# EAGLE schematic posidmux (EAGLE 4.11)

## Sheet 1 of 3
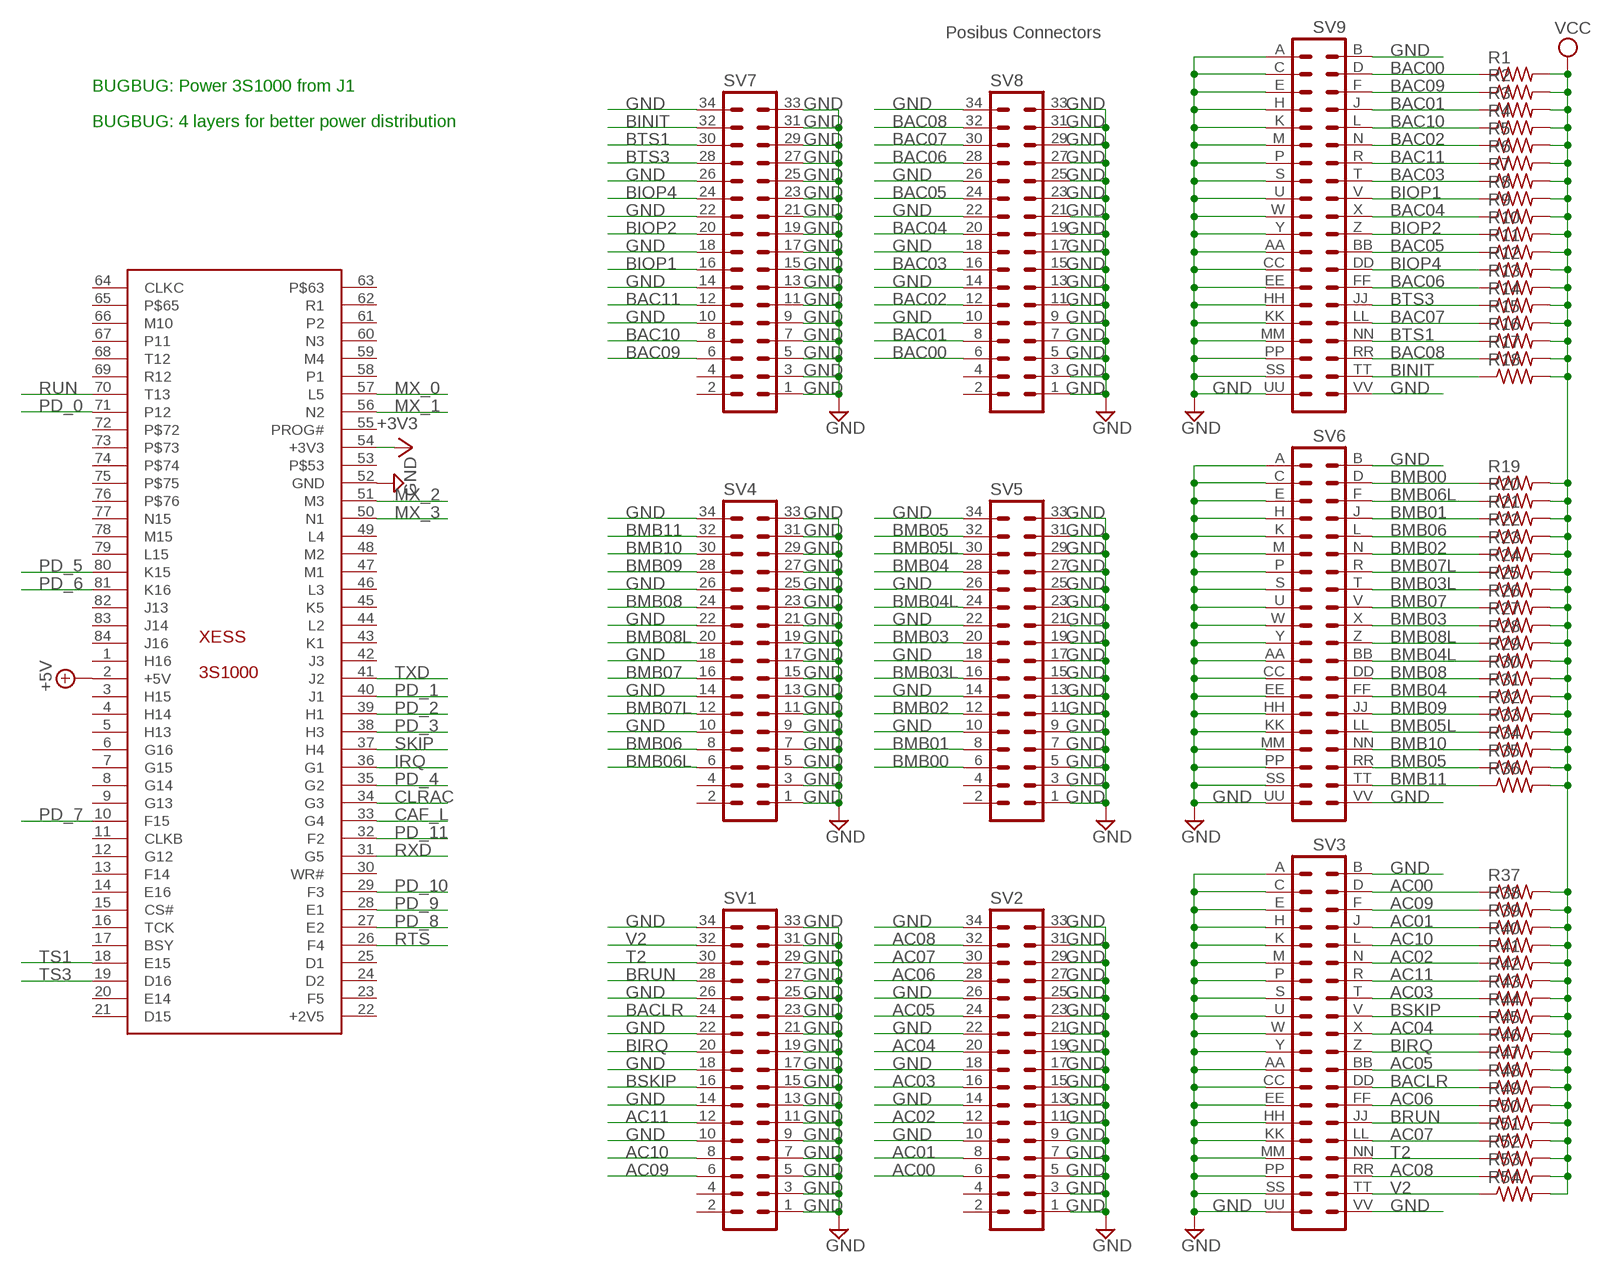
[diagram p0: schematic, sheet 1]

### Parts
R1  R-US_0207/10  [0207/10]
R2  R-US_0207/10  [0207/10]
R3  R-US_0207/10  [0207/10]
R4  R-US_0207/10  [0207/10]
R5  R-US_0207/10  [0207/10]
R6  R-US_0207/10  [0207/10]
R7  R-US_0207/10  [0207/10]
R8  R-US_0207/10  [0207/10]
R9  R-US_0207/10  [0207/10]
R10  R-US_0207/10  [0207/10]
R11  R-US_0207/10  [0207/10]
R12  R-US_0207/10  [0207/10]
R13  R-US_0207/10  [0207/10]
R14  R-US_0207/10  [0207/10]
R15  R-US_0207/10  [0207/10]
R16  R-US_0207/10  [0207/10]
R17  R-US_0207/10  [0207/10]
R18  R-US_0207/10  [0207/10]
R19  R-US_0207/10  [0207/10]
R20  R-US_0207/10  [0207/10]
R21  R-US_0207/10  [0207/10]
R22  R-US_0207/10  [0207/10]
R23  R-US_0207/10  [0207/10]
R24  R-US_0207/10  [0207/10]
R25  R-US_0207/10  [0207/10]
R26  R-US_0207/10  [0207/10]
R27  R-US_0207/10  [0207/10]
R28  R-US_0207/10  [0207/10]
R29  R-US_0207/10  [0207/10]
R30  R-US_0207/10  [0207/10]
R31  R-US_0207/10  [0207/10]
R32  R-US_0207/10  [0207/10]
R33  R-US_0207/10  [0207/10]
R34  R-US_0207/10  [0207/10]
R35  R-US_0207/10  [0207/10]
R36  R-US_0207/10  [0207/10]
R37  R-US_0207/10  [0207/10]
R38  R-US_0207/10  [0207/10]
R39  R-US_0207/10  [0207/10]
R40  R-US_0207/10  [0207/10]
R41  R-US_0207/10  [0207/10]
R42  R-US_0207/10  [0207/10]
R43  R-US_0207/10  [0207/10]
R44  R-US_0207/10  [0207/10]
R45  R-US_0207/10  [0207/10]
R46  R-US_0207/10  [0207/10]
R47  R-US_0207/10  [0207/10]
R48  R-US_0207/10  [0207/10]
R49  R-US_0207/10  [0207/10]
R50  R-US_0207/10  [0207/10]
R51  R-US_0207/10  [0207/10]
R52  R-US_0207/10  [0207/10]
R53  R-US_0207/10  [0207/10]
R54  R-US_0207/10  [0207/10]
SV1  MA17-2  [MA17-2]
SV2  MA17-2  [MA17-2]
SV3  DEC40PIN  [DEC40PIN]
SV4  MA17-2  [MA17-2]
SV5  MA17-2  [MA17-2]
SV6  DEC40PIN  [DEC40PIN]
SV7  MA17-2  [MA17-2]
SV8  MA17-2  [MA17-2]
SV9  DEC40PIN  [DEC40PIN]
XESS  3S1000  [3S1000]

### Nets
+3V3: XESS.54(+3V3) ; also sheet 3
+5V: XESS.2(+5V)
AC00: R37.1 SV2.6 SV3.D ; also sheet 3
AC01: R39.1 SV2.8 SV3.J ; also sheet 3
AC02: R41.1 SV2.12 SV3.N ; also sheet 3
AC03: R43.1 SV2.16 SV3.T ; also sheet 3
AC04: R45.1 SV2.20 SV3.X ; also sheet 3
AC05: R47.1 SV2.24 SV3.BB ; also sheet 3
AC06: R49.1 SV2.28 SV3.FF ; also sheet 3
AC07: R51.1 SV2.30 SV3.LL ; also sheet 3
AC08: R53.1 SV2.32 SV3.RR ; also sheet 3
AC09: R38.1 SV1.6 SV3.F ; also sheet 3
AC10: R40.1 SV1.8 SV3.L ; also sheet 3
AC11: R42.1 SV1.12 SV3.R ; also sheet 3
BAC00: R1.1 SV8.6 SV9.D ; also sheet 2
BAC01: R3.1 SV8.8 SV9.J ; also sheet 2
BAC02: R5.1 SV8.12 SV9.N ; also sheet 2
BAC03: R7.1 SV8.16 SV9.T ; also sheet 2
BAC04: R9.1 SV8.20 SV9.X ; also sheet 2
BAC05: R11.1 SV8.24 SV9.BB ; also sheet 2
BAC06: R13.1 SV8.28 SV9.FF ; also sheet 2
BAC07: R15.1 SV8.30 SV9.LL
BAC08: R17.1 SV8.32 SV9.RR ; also sheet 2
BAC09: R2.1 SV7.6 SV9.F ; also sheet 2
BAC10: R4.1 SV7.8 SV9.L ; also sheet 2
BAC11: R6.1 SV7.12 SV9.R ; also sheet 2
BACLR: R48.1 SV1.24 SV3.DD ; also sheet 3
BINIT: R18.1 SV7.32 SV9.TT ; also sheet 3
BIOP1: R8.1 SV7.16 SV9.V ; also sheet 3
BIOP2: R10.1 SV7.20 SV9.Z ; also sheet 3
BIOP4: R12.1 SV7.24 SV9.DD ; also sheet 3
BIRQ: R46.1 SV1.20 SV3.Z ; also sheet 3
BMB00: R19.1 SV5.6 SV6.D ; also sheet 2
BMB01: R21.1 SV5.8 SV6.J ; also sheet 2
BMB02: R23.1 SV5.12 SV6.N ; also sheet 2
BMB03: R27.1 SV5.20 SV6.X ; also sheet 2
BMB03L: R25.1 SV5.16 SV6.T ; also sheet 2
BMB04: R31.1 SV5.28 SV6.FF ; also sheet 2
BMB04L: R29.1 SV5.24 SV6.BB ; also sheet 2
BMB05: R35.1 SV5.32 SV6.RR ; also sheet 2
BMB05L: R33.1 SV5.30 SV6.LL ; also sheet 2
BMB06: R22.1 SV4.8 SV6.L ; also sheet 2
BMB06L: R20.1 SV4.6 SV6.F ; also sheet 2
BMB07: R26.1 SV4.16 SV6.V ; also sheet 2
BMB07L: R24.1 SV4.12 SV6.R ; also sheet 2
BMB08: R30.1 SV4.24 SV6.DD ; also sheet 2
BMB08L: R28.1 SV4.20 SV6.Z ; also sheet 2
BMB09: R32.1 SV4.28 SV6.JJ ; also sheet 2
BMB10: R34.1 SV4.30 SV6.NN ; also sheet 2
BMB11: R36.1 SV4.32 SV6.TT ; also sheet 2
BRUN: R50.1 SV1.28 SV3.JJ ; also sheet 3
BSKIP: R44.1 SV1.16 SV3.V ; also sheet 3
BTS1: R16.1 SV7.30 SV9.NN ; also sheet 3
BTS3: R14.1 SV7.28 SV9.JJ ; also sheet 3
CAF_L: XESS.33(G4) ; also sheet 3
CLRAC: XESS.34(G3) ; also sheet 3
GND: SV1.1 SV1.3 SV1.5 SV1.7 SV1.9 SV1.10 SV1.11 SV1.13 SV1.14 SV1.15 SV1.17 SV1.18 SV1.19 SV1.21 SV1.22 SV1.23 SV1.25 SV1.26 SV1.27 SV1.29 SV1.31 SV1.33 SV1.34 SV2.1 SV2.3 SV2.5 SV2.7 SV2.9 SV2.10 SV2.11 SV2.13 SV2.14 SV2.15 SV2.17 SV2.18 SV2.19 SV2.21 SV2.22 SV2.23 SV2.25 SV2.26 SV2.27 SV2.29 SV2.31 SV2.33 SV2.34 SV3.A SV3.AA SV3.B SV3.C SV3.CC SV3.E SV3.EE SV3.H SV3.HH SV3.K SV3.KK SV3.M SV3.MM SV3.P SV3.PP SV3.S SV3.SS SV3.U SV3.UU SV3.VV SV3.W SV3.Y SV4.1 SV4.3 SV4.5 SV4.7 SV4.9 SV4.10 SV4.11 SV4.13 SV4.14 SV4.15 SV4.17 SV4.18 SV4.19 SV4.21 SV4.22 SV4.23 SV4.25 SV4.26 SV4.27 SV4.29 SV4.31 SV4.33 SV4.34 SV5.1 SV5.3 SV5.5 SV5.7 SV5.9 SV5.10 SV5.11 SV5.13 SV5.14 SV5.15 SV5.17 SV5.18 SV5.19 SV5.21 SV5.22 SV5.23 SV5.25 SV5.26 SV5.27 SV5.29 SV5.31 SV5.33 SV5.34 SV6.A SV6.AA SV6.B SV6.C SV6.CC SV6.E SV6.EE SV6.H SV6.HH SV6.K SV6.KK SV6.M SV6.MM SV6.P SV6.PP SV6.S SV6.SS SV6.U SV6.UU SV6.VV SV6.W SV6.Y SV7.1 SV7.3 SV7.5 SV7.7 SV7.9 SV7.10 SV7.11 SV7.13 SV7.14 SV7.15 SV7.17 SV7.18 SV7.19 SV7.21 SV7.22 SV7.23 SV7.25 SV7.26 SV7.27 SV7.29 SV7.31 SV7.33 SV7.34 SV8.1 SV8.3 SV8.5 SV8.7 SV8.9 SV8.10 SV8.11 SV8.13 SV8.14 SV8.15 SV8.17 SV8.18 SV8.19 SV8.21 SV8.22 SV8.23 SV8.25 SV8.26 SV8.27 SV8.29 SV8.31 SV8.33 SV8.34 SV9.A SV9.AA SV9.B SV9.C SV9.CC SV9.E SV9.EE SV9.H SV9.HH SV9.K SV9.KK SV9.M SV9.MM SV9.P SV9.PP SV9.S SV9.SS SV9.U SV9.UU SV9.VV SV9.W SV9.Y XESS.52(GND) ; also sheet 2,3
IRQ: XESS.36(G1) ; also sheet 3
MX_0: XESS.57(L5) ; also sheet 2
MX_1: XESS.56(N2) ; also sheet 2
MX_2: XESS.51(M3) ; also sheet 2
MX_3: XESS.50(N1) ; also sheet 2
PD_0: XESS.71(P12) ; also sheet 2,3
PD_1: XESS.40(J1) ; also sheet 2,3
PD_2: XESS.39(H1) ; also sheet 2,3
PD_3: XESS.38(H3) ; also sheet 2,3
PD_4: XESS.35(G2) ; also sheet 2,3
PD_5: XESS.80(K15) ; also sheet 2,3
PD_6: XESS.81(K16) ; also sheet 2,3
PD_7: XESS.10(F15) ; also sheet 2,3
PD_8: XESS.27(E2) ; also sheet 2,3
PD_9: XESS.28(E1) ; also sheet 2,3
PD_10: XESS.29(F3) ; also sheet 2,3
PD_11: XESS.32(F2) ; also sheet 2,3
RTS: XESS.26(F4) ; also sheet 3
RUN: XESS.70(T13) ; also sheet 3
RXD: XESS.31(G5) ; also sheet 3
SKIP: XESS.37(H4) ; also sheet 3
T2: R52.1 SV1.30 SV3.NN
TS1: XESS.18(E15) ; also sheet 3
TS3: XESS.19(D16) ; also sheet 3
TXD: XESS.41(J2) ; also sheet 3
V2: R54.1 SV1.32 SV3.TT
VCC: R1.2 R2.2 R3.2 R4.2 R5.2 R6.2 R7.2 R8.2 R9.2 R10.2 R11.2 R12.2 R13.2 R14.2 R15.2 R16.2 R17.2 R18.2 R19.2 R20.2 R21.2 R22.2 R23.2 R24.2 R25.2 R26.2 R27.2 R28.2 R29.2 R30.2 R31.2 R32.2 R33.2 R34.2 R35.2 R36.2 R37.2 R38.2 R39.2 R40.2 R41.2 R42.2 R43.2 R44.2 R45.2 R46.2 R47.2 R48.2 R49.2 R50.2 R51.2 R52.2 R53.2 R54.2 ; also sheet 2,3
Unconnected: SV1.2 SV1.4 SV2.2 SV2.4 SV4.2 SV4.4 SV5.2 SV5.4 SV7.2 SV7.4 SV8.2 SV8.4 XESS.1(H16) XESS.3(H15) XESS.4(H14) XESS.5(H13) XESS.6(G16) XESS.7(G15) XESS.8(G14) XESS.9(G13) XESS.11(CLKB) XESS.12(G12) XESS.13(F14) XESS.14(E16) XESS.15(CS#) XESS.16(TCK) XESS.17(BSY) XESS.20(E14) XESS.21(D15) XESS.23(F5) XESS.24(D2) XESS.25(D1) XESS.30(WR#) XESS.42(J3) XESS.43(K1) XESS.44(L2) XESS.45(K5) XESS.46(L3) XESS.47(M1) XESS.48(M2) XESS.49(L4) XESS.53 XESS.55(PROG#) XESS.58(P1) XESS.59(M4) XESS.60(N3) XESS.61(P2) XESS.62(R1) XESS.63 XESS.64(CLKC) XESS.65 XESS.66(M10) XESS.67(P11) XESS.68(T12) XESS.69(R12) XESS.72 XESS.73 XESS.74 XESS.75 XESS.76 XESS.77(N15) XESS.78(M15) XESS.79(L15) XESS.82(J13) XESS.83(J14) XESS.84(J16)

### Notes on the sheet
- Posibus Connectors
- BUGBUG: Power 3S1000 from J1
- BUGBUG: 4 layers for better power distribution

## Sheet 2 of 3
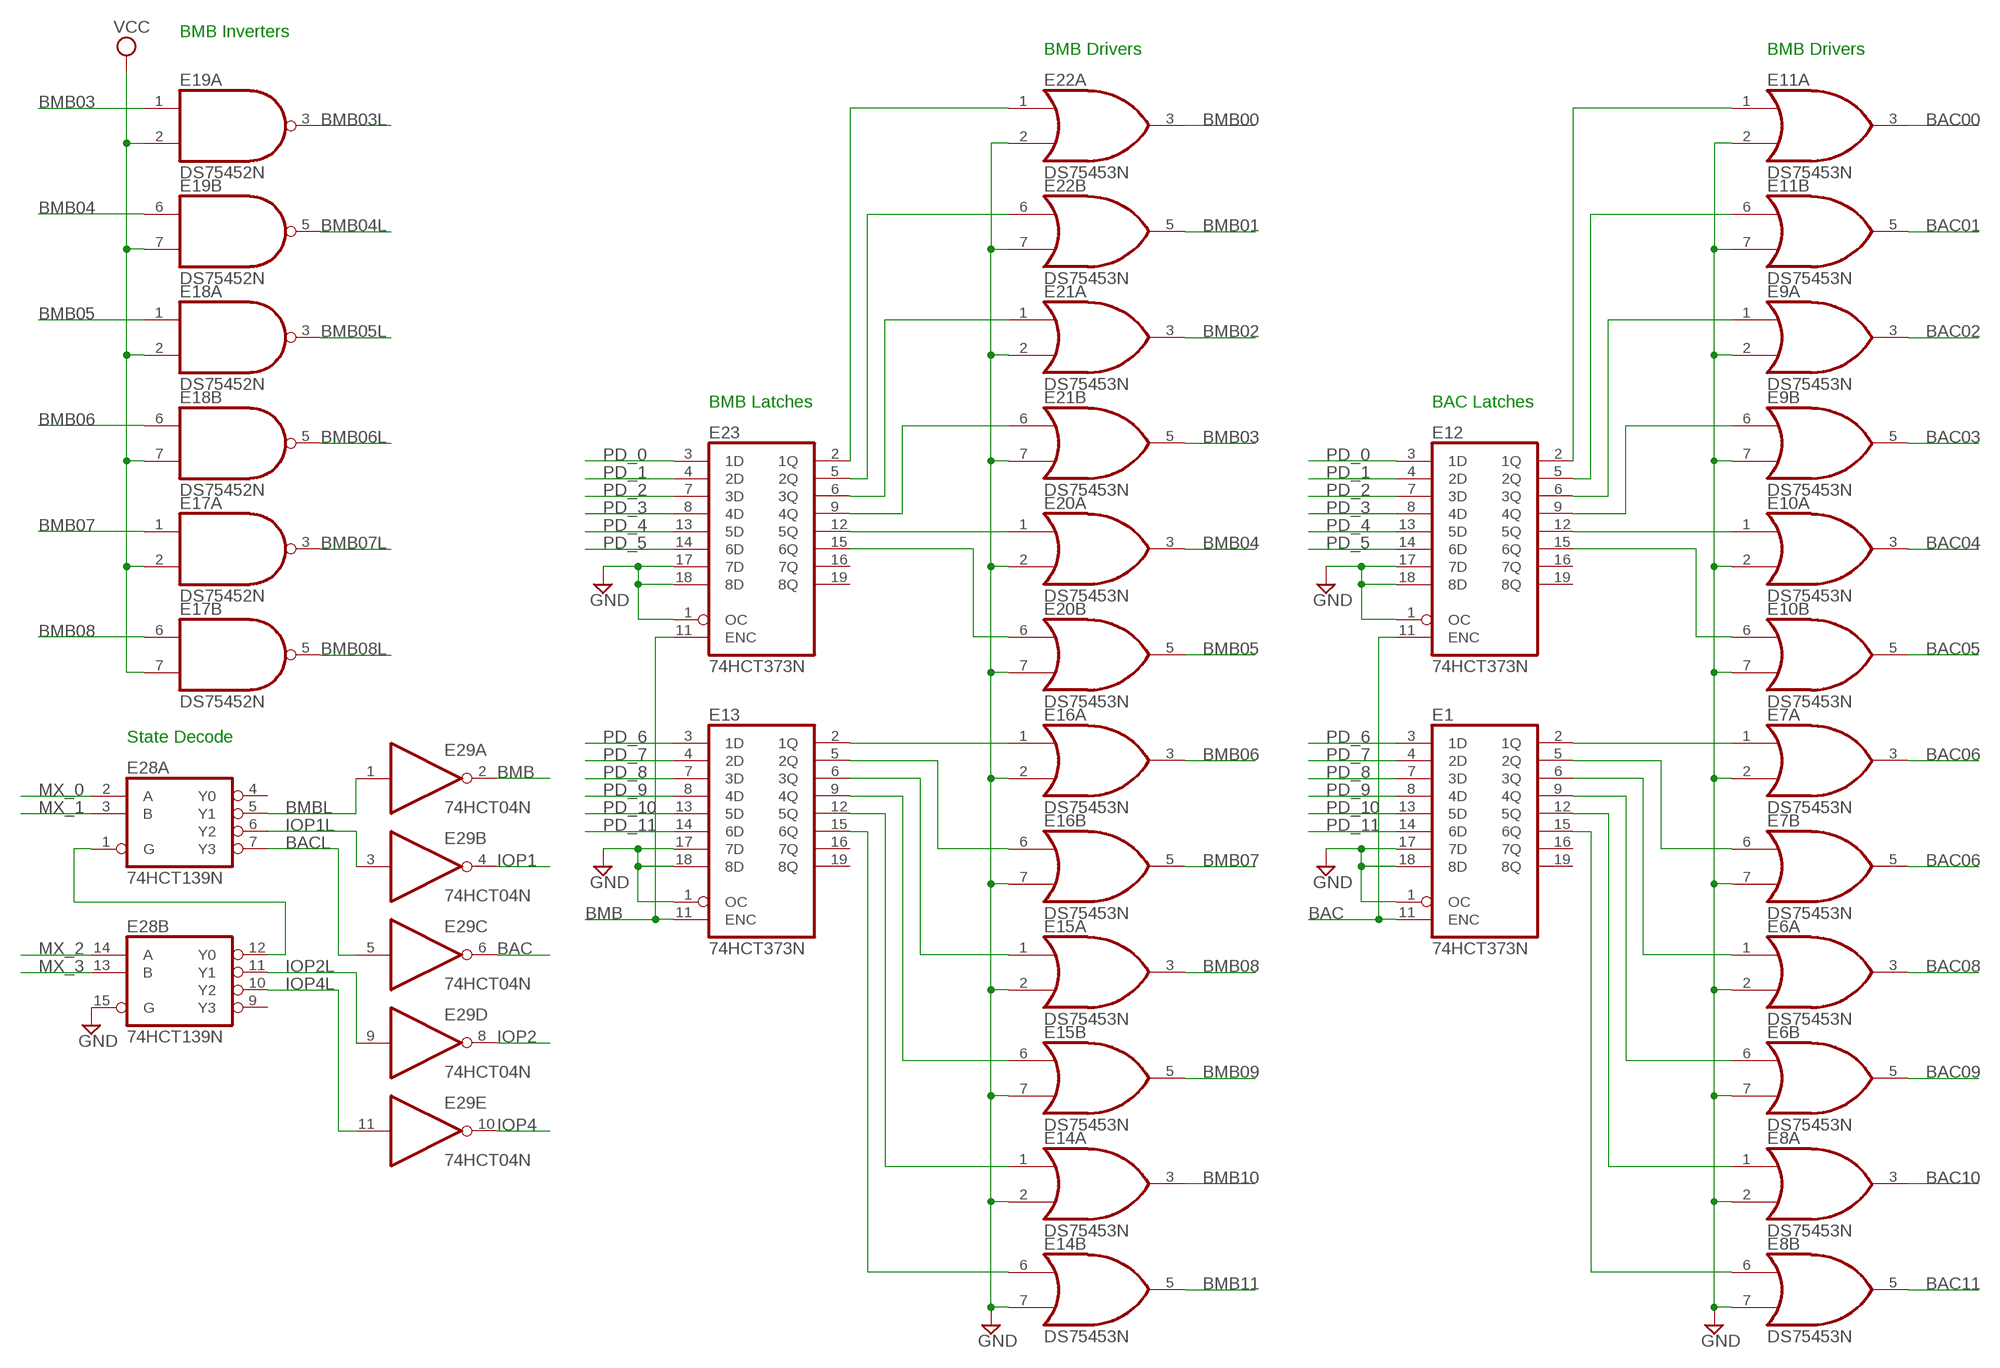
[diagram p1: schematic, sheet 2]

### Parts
E1  74HCT373N  [DIL20]
E6  DS75453N  [DIL08]
E7  DS75453N  [DIL08]
E8  DS75453N  [DIL08]
E9  DS75453N  [DIL08]
E10  DS75453N  [DIL08]
E11  DS75453N  [DIL08]
E12  74HCT373N  [DIL20]
E13  74HCT373N  [DIL20]
E14  DS75453N  [DIL08]
E15  DS75453N  [DIL08]
E16  DS75453N  [DIL08]
E17  DS75452N  [DIL08]
E18  DS75452N  [DIL08]
E19  DS75452N  [DIL08]
E20  DS75453N  [DIL08]
E21  DS75453N  [DIL08]
E22  DS75453N  [DIL08]
E23  74HCT373N  [DIL20]
E28  74HCT139N  [DIL16]
E29  74HCT04N  [DIL14]

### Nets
BAC: E1.11(ENC) E12.11(ENC) E29.6(C:O)
BAC00: E11.3(A:O) ; also sheet 1
BAC01: E11.5(B:O) ; also sheet 1
BAC02: E9.3(A:O) ; also sheet 1
BAC03: E9.5(B:O) ; also sheet 1
BAC04: E10.3(A:O) ; also sheet 1
BAC05: E10.5(B:O) ; also sheet 1
BAC06: E7.3(A:O) E7.5(B:O) ; also sheet 1
BAC08: E6.3(A:O) ; also sheet 1
BAC09: E6.5(B:O) ; also sheet 1
BAC10: E8.3(A:O) ; also sheet 1
BAC11: E8.5(B:O) ; also sheet 1
BACL: E28.7(A:Y3) E29.5(C:I)
BMB: E13.11(ENC) E23.11(ENC) E29.2(A:O)
BMB00: E22.3(A:O) ; also sheet 1
BMB01: E22.5(B:O) ; also sheet 1
BMB02: E21.3(A:O) ; also sheet 1
BMB03: E19.1(A:I0) E21.5(B:O) ; also sheet 1
BMB03L: E19.3(A:O) ; also sheet 1
BMB04: E19.6(B:I0) E20.3(A:O) ; also sheet 1
BMB04L: E19.5(B:O) ; also sheet 1
BMB05: E18.1(A:I0) E20.5(B:O) ; also sheet 1
BMB05L: E18.3(A:O) ; also sheet 1
BMB06: E16.3(A:O) E18.6(B:I0) ; also sheet 1
BMB06L: E18.5(B:O) ; also sheet 1
BMB07: E16.5(B:O) E17.1(A:I0) ; also sheet 1
BMB07L: E17.3(A:O) ; also sheet 1
BMB08: E15.3(A:O) E17.6(B:I0) ; also sheet 1
BMB08L: E17.5(B:O) ; also sheet 1
BMB09: E15.5(B:O) ; also sheet 1
BMB10: E14.3(A:O) ; also sheet 1
BMB11: E14.5(B:O) ; also sheet 1
BMBL: E28.5(A:Y1) E29.1(A:I)
GND: E1.1(OC) E1.17(7D) E1.18(8D) E6.2(A:I1) E6.7(B:I1) E7.2(A:I1) E7.7(B:I1) E8.2(A:I1) E8.7(B:I1) E9.2(A:I1) E9.7(B:I1) E10.2(A:I1) E10.7(B:I1) E11.2(A:I1) E11.7(B:I1) E12.1(OC) E12.17(7D) E12.18(8D) E13.1(OC) E13.17(7D) E13.18(8D) E14.2(A:I1) E14.7(B:I1) E15.2(A:I1) E15.7(B:I1) E16.2(A:I1) E16.7(B:I1) E20.2(A:I1) E20.7(B:I1) E21.2(A:I1) E21.7(B:I1) E22.2(A:I1) E22.7(B:I1) E23.1(OC) E23.17(7D) E23.18(8D) E28.15(B:G) ; also sheet 1,3
IOP1: E29.4(B:O) ; also sheet 3
IOP1L: E28.6(A:Y2) E29.3(B:I) ; also sheet 3
IOP2: E29.8(D:O) ; also sheet 3
IOP2L: E28.11(B:Y1) E29.9(D:I) ; also sheet 3
IOP4: E29.10(E:O) ; also sheet 3
IOP4L: E28.10(B:Y2) E29.11(E:I) ; also sheet 3
MX_0: E28.2(A:A) ; also sheet 1
MX_00XX: E28.1(A:G) E28.12(B:Y0)
MX_1: E28.3(A:B) ; also sheet 1
MX_2: E28.14(B:A) ; also sheet 1
MX_3: E28.13(B:B) ; also sheet 1
N$1: E22.1(A:I0) E23.2(1Q)
N$2: E22.6(B:I0) E23.5(2Q)
N$3: E21.1(A:I0) E23.6(3Q)
N$4: E21.6(B:I0) E23.9(4Q)
N$5: E20.1(A:I0) E23.12(5Q)
N$6: E13.15(6Q) E14.6(B:I0)
N$7: E13.12(5Q) E14.1(A:I0)
N$8: E13.9(4Q) E15.6(B:I0)
N$9: E13.6(3Q) E15.1(A:I0)
N$10: E13.5(2Q) E16.6(B:I0)
N$11: E13.2(1Q) E16.1(A:I0)
N$12: E20.6(B:I0) E23.15(6Q)
N$13: E11.1(A:I0) E12.2(1Q)
N$14: E11.6(B:I0) E12.5(2Q)
N$21: E9.1(A:I0) E12.6(3Q)
N$22: E9.6(B:I0) E12.9(4Q)
N$23: E10.1(A:I0) E12.12(5Q)
N$24: E1.15(6Q) E8.6(B:I0)
N$25: E1.12(5Q) E8.1(A:I0)
N$26: E1.9(4Q) E6.6(B:I0)
N$27: E1.6(3Q) E6.1(A:I0)
N$28: E1.5(2Q) E7.6(B:I0)
N$29: E10.6(B:I0) E12.15(6Q)
N$30: E1.2(1Q) E7.1(A:I0)
PD_0: E12.3(1D) E23.3(1D) ; also sheet 1,3
PD_1: E12.4(2D) E23.4(2D) ; also sheet 1,3
PD_2: E12.7(3D) E23.7(3D) ; also sheet 1,3
PD_3: E12.8(4D) E23.8(4D) ; also sheet 1,3
PD_4: E12.13(5D) E23.13(5D) ; also sheet 1,3
PD_5: E12.14(6D) E23.14(6D) ; also sheet 1,3
PD_6: E1.3(1D) E13.3(1D) ; also sheet 1,3
PD_7: E1.4(2D) E13.4(2D) ; also sheet 1,3
PD_8: E1.7(3D) E13.7(3D) ; also sheet 1,3
PD_9: E1.8(4D) E13.8(4D) ; also sheet 1,3
PD_10: E1.13(5D) E13.13(5D) ; also sheet 1,3
PD_11: E1.14(6D) E13.14(6D) ; also sheet 1,3
VCC: E17.2(A:I1) E17.7(B:I1) E18.2(A:I1) E18.7(B:I1) E19.2(A:I1) E19.7(B:I1) ; also sheet 1,3
Unconnected: E1.16(7Q) E1.19(8Q) E12.16(7Q) E12.19(8Q) E13.16(7Q) E13.19(8Q) E23.16(7Q) E23.19(8Q) E28.4(A:Y0) E28.9(B:Y3) E29.12(F:O) E29.13(F:I)

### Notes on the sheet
- BMB Inverters
- BMB Drivers | BMB Drivers
- BMB Latches | BAC Latches
- State Decode

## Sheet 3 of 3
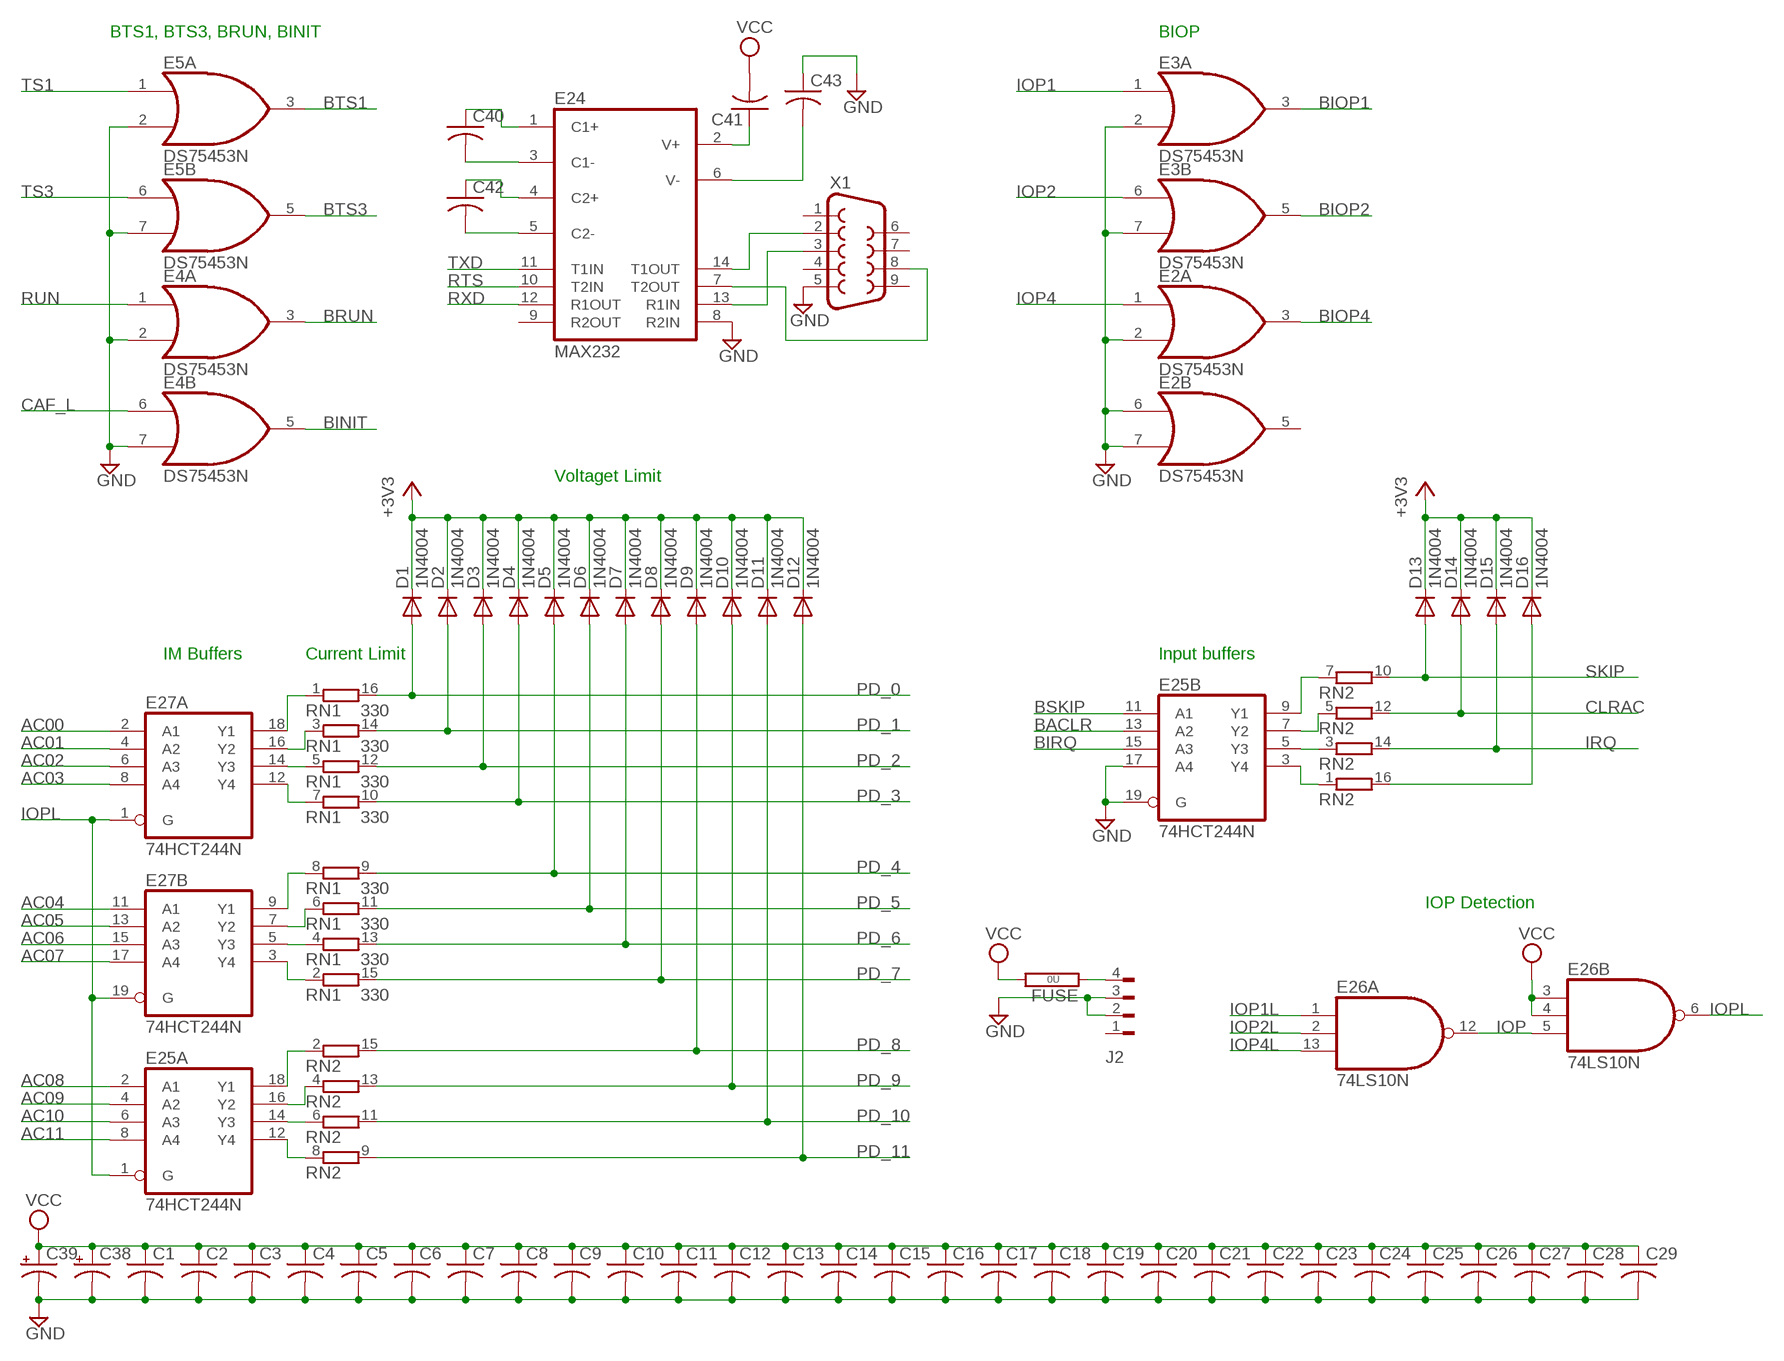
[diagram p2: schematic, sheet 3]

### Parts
C1  C-US050-025X075  [C050-025X075]
C2  C-US050-025X075  [C050-025X075]
C3  C-US050-025X075  [C050-025X075]
C4  C-US050-025X075  [C050-025X075]
C5  C-US050-025X075  [C050-025X075]
C6  C-US050-025X075  [C050-025X075]
C7  C-US050-025X075  [C050-025X075]
C8  C-US050-025X075  [C050-025X075]
C9  C-US050-025X075  [C050-025X075]
C10  C-US050-025X075  [C050-025X075]
C11  C-US050-025X075  [C050-025X075]
C12  C-US050-025X075  [C050-025X075]
C13  C-US050-025X075  [C050-025X075]
C14  C-US050-025X075  [C050-025X075]
C15  C-US050-025X075  [C050-025X075]
C16  C-US050-025X075  [C050-025X075]
C17  C-US050-025X075  [C050-025X075]
C18  C-US050-025X075  [C050-025X075]
C19  C-US050-025X075  [C050-025X075]
C20  C-US050-025X075  [C050-025X075]
C21  C-US050-025X075  [C050-025X075]
C22  C-US050-025X075  [C050-025X075]
C23  C-US050-025X075  [C050-025X075]
C24  C-US050-025X075  [C050-025X075]
C25  C-US050-025X075  [C050-025X075]
C26  C-US050-025X075  [C050-025X075]
C27  C-US050-025X075  [C050-025X075]
C28  C-US050-025X075  [C050-025X075]
C29  C-US050-025X075  [C050-025X075]
C38  CPOL-USE22-6AXIAL  [E22-6]
C39  CPOL-USE22-6AXIAL  [E22-6]
C40  C-US050-025X075  [C050-025X075]
C41  C-US050-025X075  [C050-025X075]
C42  C-US050-025X075  [C050-025X075]
C43  C-US050-025X075  [C050-025X075]
D1  1N4004  [DO41-10]
D2  1N4004  [DO41-10]
D3  1N4004  [DO41-10]
D4  1N4004  [DO41-10]
D5  1N4004  [DO41-10]
D6  1N4004  [DO41-10]
D7  1N4004  [DO41-10]
D8  1N4004  [DO41-10]
D9  1N4004  [DO41-10]
D10  1N4004  [DO41-10]
D11  1N4004  [DO41-10]
D12  1N4004  [DO41-10]
D13  1N4004  [DO41-10]
D14  1N4004  [DO41-10]
D15  1N4004  [DO41-10]
D16  1N4004  [DO41-10]
E2  DS75453N  [DIL08]
E3  DS75453N  [DIL08]
E4  DS75453N  [DIL08]
E5  DS75453N  [DIL08]
E24  MAX232  [DIL16]
E25  74HCT244N  [DIL20]
E26  74LS10N  [DIL14]
E27  74HCT244N  [DIL20]
FUSE  0R  [0R/10]
J2  FLOPPY-4  [FLOPPY-4]
RN1  330  8R-P  [DIL16]
RN2  8R-P  [DIL16]
X1  F09HP  [F09HP]

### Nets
+3V3: D1.C D2.C D3.C D4.C D5.C D6.C D7.C D8.C D9.C D10.C D11.C D12.C D13.C D14.C D15.C D16.C ; also sheet 1
AC00: E27.2(A:A1) ; also sheet 1
AC01: E27.4(A:A2) ; also sheet 1
AC02: E27.6(A:A3) ; also sheet 1
AC03: E27.8(A:A4) ; also sheet 1
AC04: E27.11(B:A1) ; also sheet 1
AC05: E27.13(B:A2) ; also sheet 1
AC06: E27.15(B:A3) ; also sheet 1
AC07: E27.17(B:A4) ; also sheet 1
AC08: E25.2(A:A1) ; also sheet 1
AC09: E25.4(A:A2) ; also sheet 1
AC10: E25.6(A:A3) ; also sheet 1
AC11: E25.8(A:A4) ; also sheet 1
BACLR: E25.13(B:A2) ; also sheet 1
BINIT: E4.5(B:O) ; also sheet 1
BIOP1: E3.3(A:O) ; also sheet 1
BIOP2: E3.5(B:O) ; also sheet 1
BIOP4: E2.3(A:O) ; also sheet 1
BIRQ: E25.15(B:A3) ; also sheet 1
BRUN: E4.3(A:O) ; also sheet 1
BSKIP: E25.11(B:A1) ; also sheet 1
BTS1: E5.3(A:O) ; also sheet 1
BTS3: E5.5(B:O) ; also sheet 1
CAF_L: E4.6(B:I0) ; also sheet 1
CLRAC: D14.A RN2.12 ; also sheet 1
GND: C1.2 C2.2 C3.2 C4.2 C5.2 C6.2 C7.2 C8.2 C9.2 C10.2 C11.2 C12.2 C13.2 C14.2 C15.2 C16.2 C17.2 C18.2 C19.2 C20.2 C21.2 C22.2 C23.2 C24.2 C25.2 C26.2 C27.2 C28.2 C29.2 C38.- C39.- C43.1 E2.2(A:I1) E2.6(B:I0) E2.7(B:I1) E3.2(A:I1) E3.7(B:I1) E4.2(A:I1) E4.7(B:I1) E5.2(A:I1) E5.7(B:I1) E24.8(R2IN) E25.17(B:A4) E25.19(B:G) J2.2 J2.3 X1.5 ; also sheet 1,2
IOP: E26.5(B:I2) E26.12(A:O)
IOP1: E3.1(A:I0) ; also sheet 2
IOP1L: E26.1(A:I0) ; also sheet 2
IOP2: E3.6(B:I0) ; also sheet 2
IOP2L: E26.2(A:I1) ; also sheet 2
IOP4: E2.1(A:I0) ; also sheet 2
IOP4L: E26.13(A:I2) ; also sheet 2
IOPL: E25.1(A:G) E26.6(B:O) E27.1(A:G) E27.19(B:G)
IRQ: D15.A RN2.14 ; also sheet 1
N$15: E27.18(A:Y1) RN1.1
N$16: E27.16(A:Y2) RN1.3
N$17: E27.14(A:Y3) RN1.5
N$18: E27.12(A:Y4) RN1.7
N$19: E27.9(B:Y1) RN1.8
N$20: E27.7(B:Y2) RN1.6
N$31: E27.5(B:Y3) RN1.4
N$32: E27.3(B:Y4) RN1.2
N$33: E25.16(A:Y2) RN2.4
N$34: E25.18(A:Y1) RN2.2
N$35: E25.14(A:Y3) RN2.6
N$36: E25.12(A:Y4) RN2.8
N$37: E25.9(B:Y1) RN2.7
N$38: E25.7(B:Y2) RN2.5
N$39: E25.5(B:Y3) RN2.3
N$40: E25.3(B:Y4) RN2.1
N$41 [Supply]: FUSE.1 J2.4
N$42: D16.A RN2.16
N$43: E24.14(T1OUT) X1.2
N$44: E24.7(T2OUT) X1.8
N$45: E24.13(R1IN) X1.3
N$46: C42.2 E24.5(C2-)
N$47: C42.1 E24.4(C2+)
N$48: C40.2 E24.3(C1-)
N$49: C40.1 E24.1(C1+)
N$50: C41.1 E24.2(V+)
N$51: C43.2 E24.6(V-)
PD_0: D1.A RN1.16 ; also sheet 1,2
PD_1: D2.A RN1.14 ; also sheet 1,2
PD_2: D3.A RN1.12 ; also sheet 1,2
PD_3: D4.A RN1.10 ; also sheet 1,2
PD_4: D5.A RN1.9 ; also sheet 1,2
PD_5: D6.A RN1.11 ; also sheet 1,2
PD_6: D7.A RN1.13 ; also sheet 1,2
PD_7: D8.A RN1.15 ; also sheet 1,2
PD_8: D9.A RN2.15 ; also sheet 1,2
PD_9: D10.A RN2.13 ; also sheet 1,2
PD_10: D11.A RN2.11 ; also sheet 1,2
PD_11: D12.A RN2.9 ; also sheet 1,2
RTS: E24.10(T2IN) ; also sheet 1
RUN: E4.1(A:I0) ; also sheet 1
RXD: E24.12(R1OUT) ; also sheet 1
SKIP: D13.A RN2.10 ; also sheet 1
TS1: E5.1(A:I0) ; also sheet 1
TS3: E5.6(B:I0) ; also sheet 1
TXD: E24.11(T1IN) ; also sheet 1
VCC: C1.1 C2.1 C3.1 C4.1 C5.1 C6.1 C7.1 C8.1 C9.1 C10.1 C11.1 C12.1 C13.1 C14.1 C15.1 C16.1 C17.1 C18.1 C19.1 C20.1 C21.1 C22.1 C23.1 C24.1 C25.1 C26.1 C27.1 C28.1 C29.1 C38.+ C39.+ C41.2 E26.3(B:I0) E26.4(B:I1) FUSE.2 ; also sheet 1,2
Unconnected: E2.5(B:O) E24.9(R2OUT) E26.8(C:O) E26.9(C:I0) E26.10(C:I1) E26.11(C:I2) J2.1 X1.1 X1.4 X1.6 X1.7 X1.9

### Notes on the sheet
- BTS1, BTS3, BRUN, BINIT | BIOP
- Voltaget Limit
- IM Buffers | Current Limit | Input buffers
- IOP Detection

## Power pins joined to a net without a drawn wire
+2V5: XESS.22(+2V5)
GND: E1.10(GND) E2.4(P:GND) E3.4(P:GND) E4.4(P:GND) E5.4(P:GND) E6.4(P:GND) E7.4(P:GND) E8.4(P:GND) E9.4(P:GND) E10.4(P:GND) E11.4(P:GND) E12.10(GND) E13.10(GND) E14.4(P:GND) E15.4(P:GND) E16.4(P:GND) E17.4(P:GND) E18.4(P:GND) E19.4(P:GND) E20.4(P:GND) E21.4(P:GND) E22.4(P:GND) E23.10(GND) E24.15(GND) E25.10(P:GND) E26.7(P:GND) E27.10(P:GND) E28.8(P:GND) E29.7(P:GND)
VCC: E1.20(VCC) E2.8(P:VCC) E3.8(P:VCC) E4.8(P:VCC) E5.8(P:VCC) E6.8(P:VCC) E7.8(P:VCC) E8.8(P:VCC) E9.8(P:VCC) E10.8(P:VCC) E11.8(P:VCC) E12.20(VCC) E13.20(VCC) E14.8(P:VCC) E15.8(P:VCC) E16.8(P:VCC) E17.8(P:VCC) E18.8(P:VCC) E19.8(P:VCC) E20.8(P:VCC) E21.8(P:VCC) E22.8(P:VCC) E23.20(VCC) E24.16(VCC) E25.20(P:VCC) E26.14(P:VCC) E27.20(P:VCC) E28.16(P:VCC) E29.14(P:VCC)

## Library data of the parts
C1-C29 C40-C43 = rcl:C-US: CAPACITOR, American symbol
C38 C39 = rcl:CPOL-US: POLARIZED CAPACITOR, American symbol
D1-D16 = diode:1N4004: DIODE
E1 E12 E13 E23 = 74xx-jameco:74*373: Octal D type transparent LATCH
E2-E11 E14-E16 E20-E22 = 74xx-jameco:DS75453: Quad 2-input OR gate, open collector output
E17-E19 = 74xx-jameco:DS75452: Quad 2-input NAND gate, open collector output
E24 = maxim:MAX232: RS232 TRANSEIVER
E25 E27 = 74xx-jameco:74*244: Octal BUFFER and LINE DRIVER, 3-state
E26 = 74xx-jameco:74*10: Triple 3-input NAND gate
E28 = 74xx-jameco:74*139: Dual 2-line to 4-line DECODER/DEMULTIPLEXER
E29 = 74xx-jameco:74*04: Hex INVERTER
FUSE = jumper:0R: Bridge 0R 10mm
J2 = con-amp:FLOPPY-4: MATE N-LOCK
R1-R54 = rcl:R-US_: RESISTOR, American symbol
RN1 RN2 = resistor-dil:8R-P: DIL RESISTOR
SV1 SV2 SV4 SV5 SV7 SV8 = con-lstb:MA17-2: PIN HEADER
SV3 SV6 SV9 = dec-con:DEC40PIN: PIN HEADER
X1 = con-subd:F09: SUB-D
XESS = xess:3S1000

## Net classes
1 Supply: width 1.905 mm, drill 0.508 mm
